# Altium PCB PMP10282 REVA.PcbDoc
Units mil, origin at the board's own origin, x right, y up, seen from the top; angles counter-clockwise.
Board outline 3149.61 x 1181.1 mil, 4 copper layers (Top Layer, MidLayer1, MidLayer2, Bottom Layer), stack 62.2 mil thick; 58 components, 35 nets, 158 pads, 79 vias.
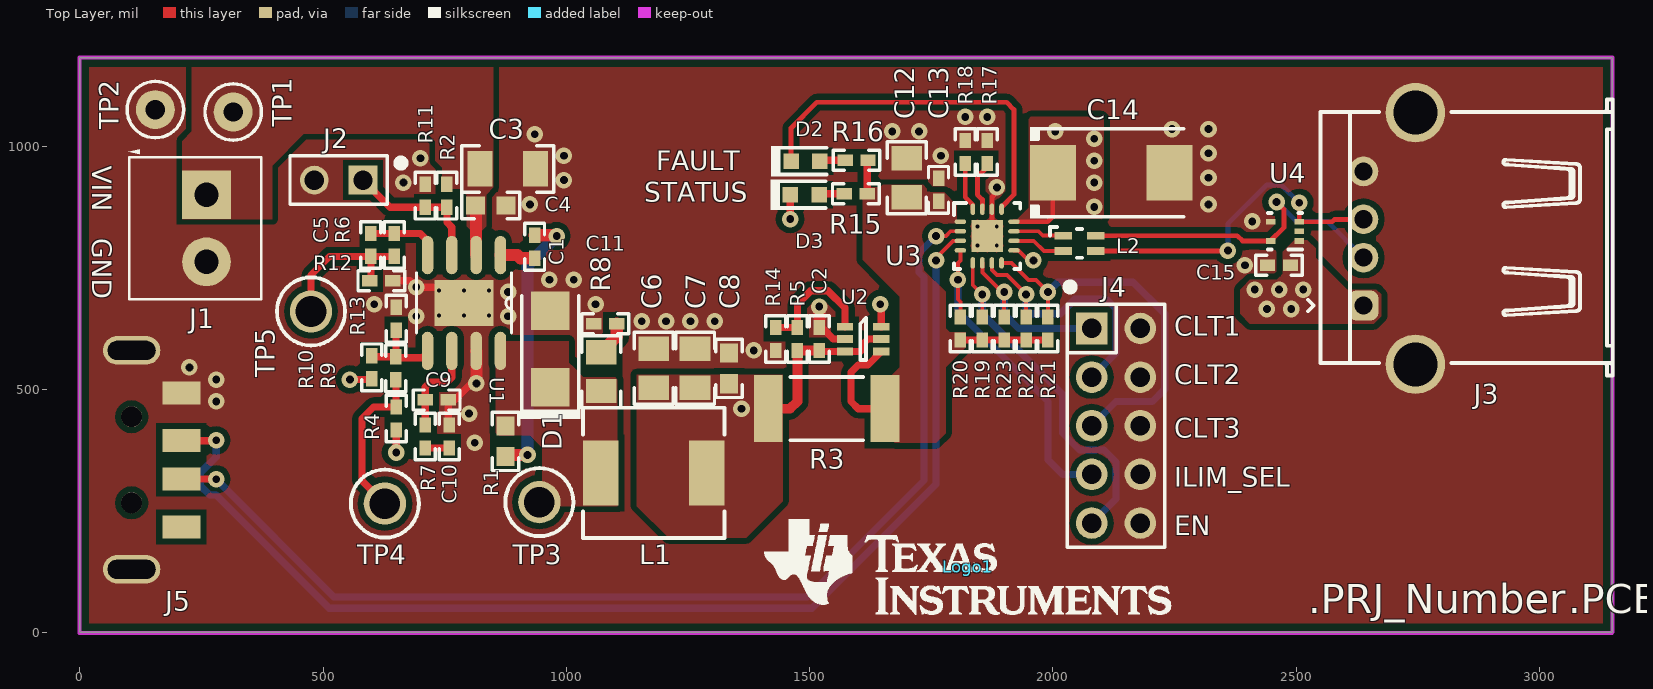
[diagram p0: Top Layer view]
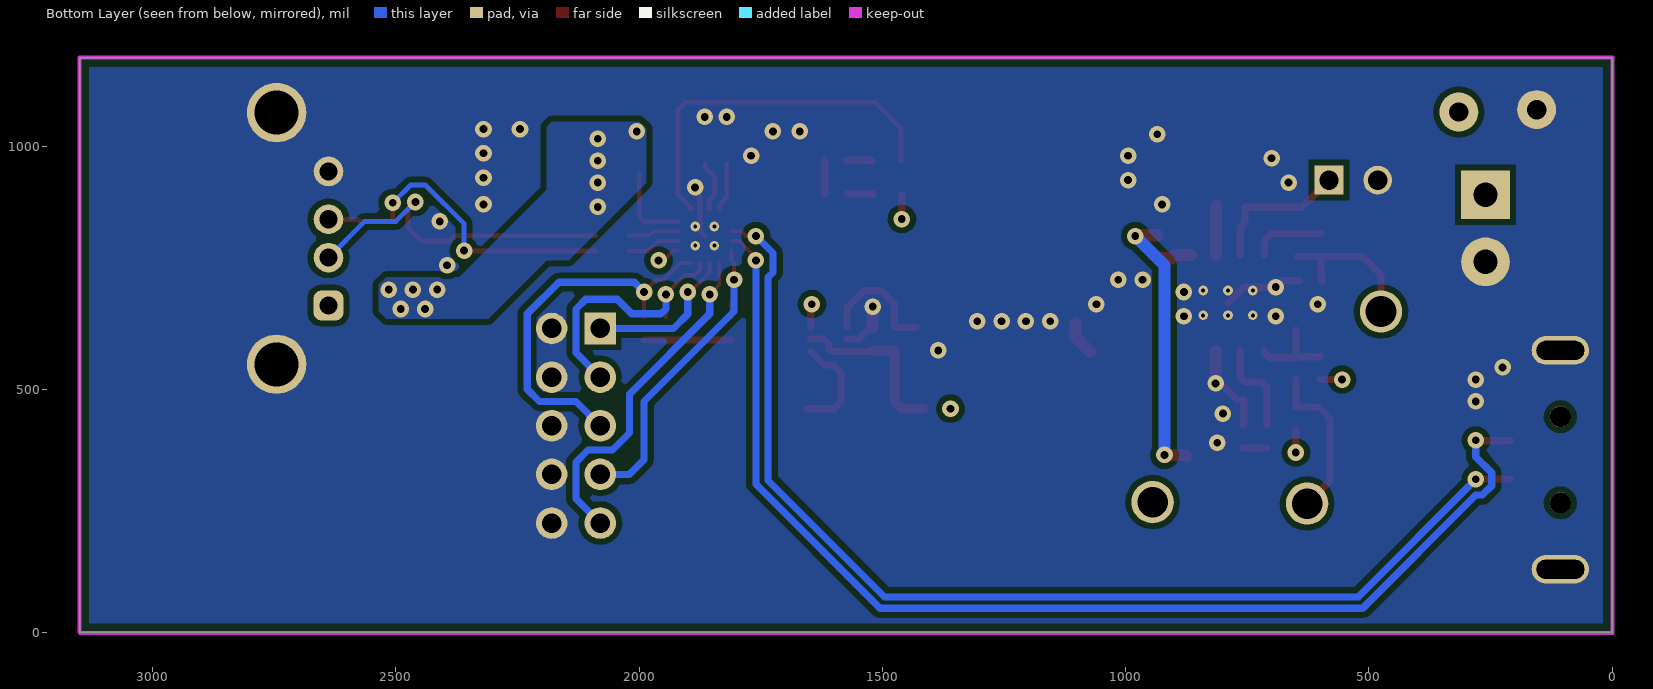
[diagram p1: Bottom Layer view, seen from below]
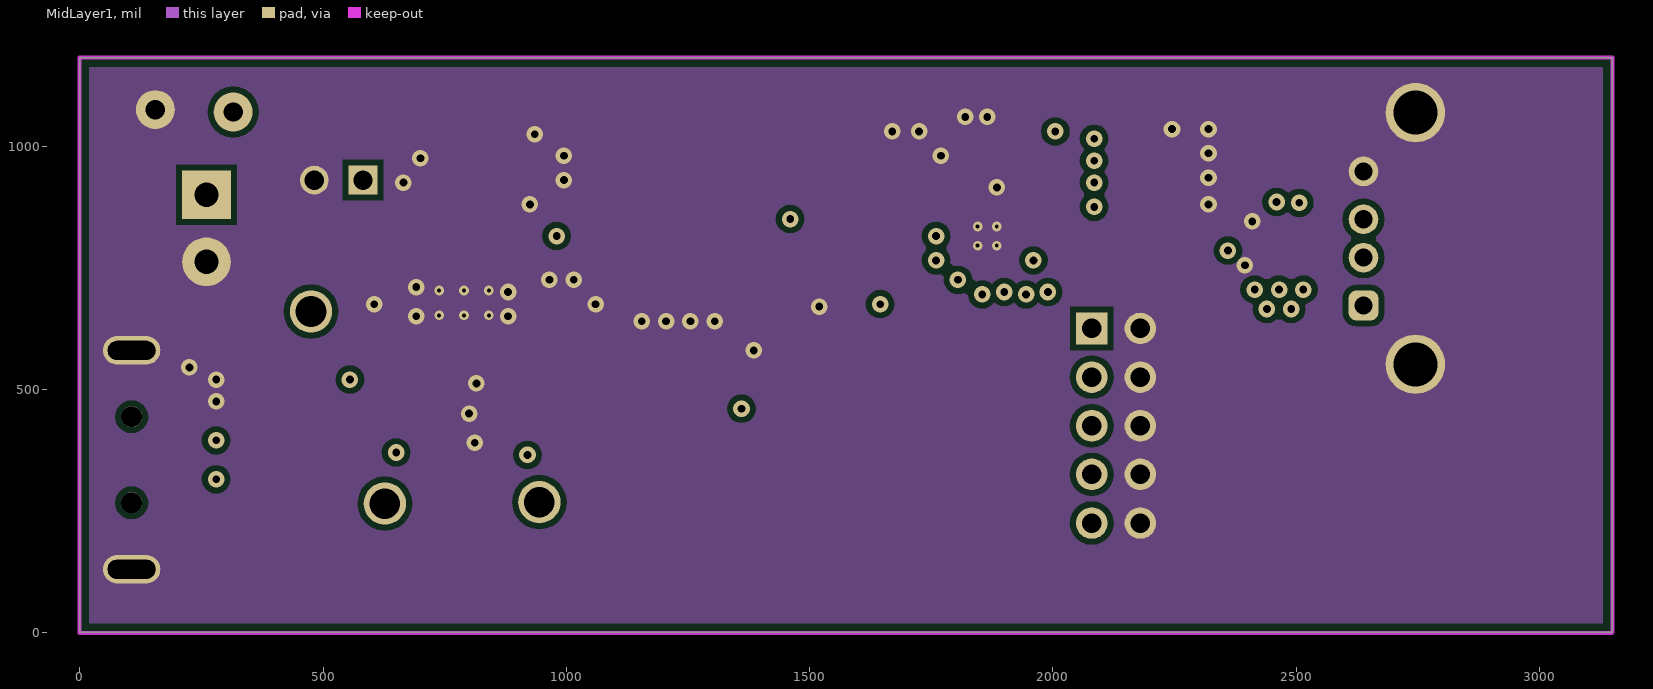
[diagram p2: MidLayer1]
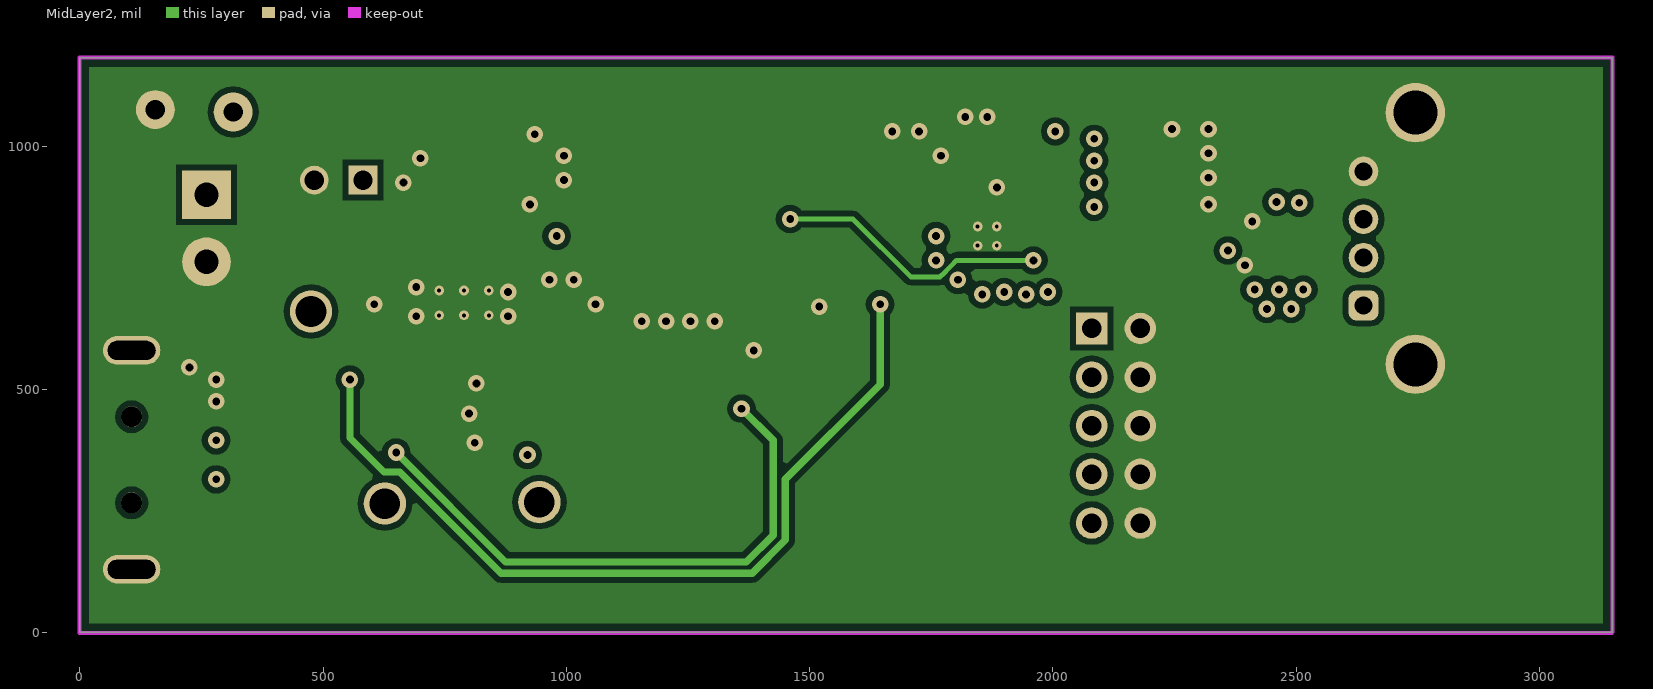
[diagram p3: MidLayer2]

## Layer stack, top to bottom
Top Layer: signal copper 1.4
Dielectric: core 22, FR-4, Dk 4.8
MidLayer1: signal copper 1.4
Dielectric: prepreg 12.6, FR-4, Dk 4.8
MidLayer2: signal copper 1.4
Dielectric: core 22, FR-4, Dk 4.8
Bottom Layer: signal copper 1.4

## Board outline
0,0 3149.61,0 3149.61,1181.1 0,1181.1

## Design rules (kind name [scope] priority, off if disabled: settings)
AcuteAngle [All] p1: minimum=4.50000000000000E+0001 checktracksonly=FALSE
AssemblyTestPointUsage [All] p1: valid=2
Clearance Clearance_BoardEdge_MountingHoles [OnCopper and InComponentClass('Mounting Holes') vs IsKeepOut] p1: gap=25
Clearance Clearance_BoardEdge_Poly [OnCopper and InPoly vs IsKeepOut] p2: gap=15
Clearance Clearance_BoardEdge [OnCopper and Not InComponentClass('Logo') and not InComponentClass('FiducialMark') and not InRegion(1000,500,4000,800) and Not IsKeepout vs IsKeepOut] p3: gap=25
Clearance Clearance_Poly [InPolygon] p4: gap=12
Clearance [All] p5: gap=8
ComponentClearance ComponentClearance_Shunt [InComponentClass('Header') vs InComponentClass('Shunt')] p1: gap=0 collisioncheckmode=3 verticalgap=0 showdistances=FALSE
ComponentClearance ComponentClearance_Logo [InComponentClass('Logo')] p2: gap=0 collisioncheckmode=3 verticalgap=0 showdistances=FALSE
ComponentClearance ComponentClearance_ScrewToNut [(HasFootprint('NY PMS 440 0025 PH')) vs (HasFootprint('Keystone_1902C'))] p3: gap=5 collisioncheckmode=3 verticalgap=10 showdistances=FALSE
ComponentClearance ComponentClearance_MountingHoles [InComponentClass('Mounting Holes')] p4: gap=250 collisioncheckmode=3 verticalgap=100000 showdistances=FALSE
ComponentClearance ComponentClearance_SmallPassives [HasFootprint('0201*') or HasFootprint('0402*') or HasFootprint('0508') or HasFootprint('0603*') or HasFootprint('0612') or HasFootprint('0805*') or HasFootprint('0815*') or HasFootprint('0830*') or HasFootprint('1206*') or HasFootprint('1210*') or HasFootprint('1808*') or HasFootprint('1812*') or HasFootprint('1825*') or HasFootprint('2010*') or HasFootprint('2220*') or HasFootprint('2225*') or HasFootprint('2512*') or HasFootprint('2728*') or HasFootprint('3518*') vs HasFootprint('0201*') or HasFootprint('0402*') or HasFootprint('0508') or HasFootprint('0603*') or HasFootprint('0612') or HasFootprint('0805*') or HasFootprint('0815*') or HasFootprint('0830*') or HasFootprint('1206*') or HasFootprint('1210*') or HasFootprint('1808*') or HasFootprint('1812*') or HasFootprint('1825*') or HasFootprint('2010*') or HasFootprint('2220*') or HasFootprint('2225*') or HasFootprint('2512*') or HasFootprint('2728*') or HasFootprint('3518*')] p5: gap=20 collisioncheckmode=3 verticalgap=10 showdistances=FALSE
ComponentClearance ComponentClearance_THtoSMT [IsThruComponent vs IsSMTComponent] p6: gap=25 collisioncheckmode=3 verticalgap=30 showdistances=FALSE
ComponentClearance ComponentClearance_THtoTH [IsThruComponent vs IsThruComponent] p7: gap=50 collisioncheckmode=3 verticalgap=30 showdistances=FALSE
ComponentClearance [All] p8: gap=20 collisioncheckmode=3 verticalgap=10 showdistances=FALSE
DiffPairsRouting [All] p1: maxlimit=100 minlimit=10 mostfreqgap=10 maxuncoupledlength=1000
FabricationTestPointUsage TestPointUsage [All] p1: valid=2 allowmultiple=FALSE
FabricationTestpoint Testpoint [All] p1: side=3 testpointundercomponent=TRUE minsize=40 maxsize=100 preferedsize=60 minholesize=0 maxholesize=40 preferedholesize=32 testpointgrid=1 allowsidetop=TRUE allowsidebottom=TRUE usegrid=TRUE gridtolerance=0.01
FanoutControl Fanout_LCC [IsLCC] p1: bgadir=Out bgaviamode=Centered fanoutstyle=Auto fanoutdirection=Alternating viagrid=1 // Fanout_LCC (Default Rule)
FanoutControl Fanout_BGA [IsBGA] p2: bgadir=Out bgaviamode=Centered fanoutstyle=Auto fanoutdirection=Alternating viagrid=1 // Fanout_BGA (Default Rule)
FanoutControl Fanout_Default [All] p4: bgadir=Out bgaviamode=Centered fanoutstyle=Auto fanoutdirection=Alternating viagrid=1 // Fanout_Default (Default Rule)
FanoutControl Fanout_Small [(CompPinCount < 5)] p5: bgadir=Out bgaviamode=Centered fanoutstyle=Auto fanoutdirection=OutThenIn viagrid=1 // Fanout_Small (Default Rule)
HoleSize [All] p1: absolutevalues=TRUE maxlimit=251 minlimit=8 maxpercent=80.000 minpercent=20.000
MinimumAnnularRing MinimumAnnularRing_ThermalPadVias [IsVia and InAnyComponent] p1: minimumring=5.91
MinimumAnnularRing [All] p2: minimumring=9
MinimumSolderMaskSliver MinimumSolderMaskSliver_Logo [InComponentClass('Logo') vs InComponentClass('Logo')] p1: minsoldermaskwidth=0.7
MinimumSolderMaskSliver [All] p2: minsoldermaskwidth=3
PlaneClearance [All] p1: clearance=15
PlaneConnect [All] p1: planeconnectstyle=Direct reliefexpansion=10 reliefentries=4 reliefconductorwidth=10 reliefairgap=10
PolygonConnect [All] p1: connectstyle=Direct reliefconductorwidth=10 reliefentries=4 polygonreliefangle="90 Angle" airgapwidth=10
RoutingVias ThermalPadVias [IsVia and InAnyComponent] p1: holewidth=7.87 width=19.68 viastyle="Through Hole" minholewidth=7.87 minwidth=19.68 maxholewidth=12.99 maxwidth=23.62
RoutingVias [All] p2: holewidth=16 width=34 viastyle="Through Hole" minholewidth=7.87 minwidth=26 maxholewidth=40 maxwidth=65
SMDToCorner [All] p1: distance=30000
SilkToSilkClearance [All] p1: silktosilkclearance=0
SilkscreenOverComponentPads [All] p1: minsilkscreentomaskgap=0
SolderMaskExpansion [All] p1: expansion=1.97
Width [All] p1: maxlimit=100 minlimit=6 preferedwidth=10 checkconnectedcopper=TRUE
13 further rules are at their usual default settings.

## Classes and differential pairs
component class Logo: Logo1
component class Header: J2

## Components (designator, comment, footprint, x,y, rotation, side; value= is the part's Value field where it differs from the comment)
C1 "C1005X7R1H104K050BB" 0402 934.5,792.99 r270 top
C2 "C1005X7R1H104K050BB" 0402 1520,603.19 r90 top
C3 "GRM31CR71H475KA12L" 1206 879.5,952.99 r0 top
C4 "UMK107AB7105KA-T" 0603 844.5,877.99 r0 top
C5 "" 0402 598.12,796.77 r270 top
C6 "GRM21BR61A226ME44" 0805_HV 1179.5,542.99 r90 top
C7 "GRM21BR61A226ME44" 0805_HV 1264.5,542.99 r90 top
C8 "UMK107AB7105KA-T" 0603 1334.5,542.99 r90 top
C9 "GRM1535C1H101JDD5D" 0402 733.28,477.99 r0 top
C10 "C1005C0G1E102J" 0402 759.5,402.99 r90 top
C11 "" 0402 1080,635 r180 top
C12 "GRM21BR71A106KE51L" 0805_HV 1700,935 r90 top
C13 "C1005X7R1H104K050BB" 0402 1765,910 r90 top
C14 "10TPB150ML" TPB_D4 2120,945 r0 top
C15 "C1005X7R1H104K050BB" 0402 2465,755 r180 top
D1 "B340LA-13-F" SMA 966.52,582.63 r90 top
D2 "LTST-C190GKT" LED_LTST-C190 1491.59,969 r180 top
D3 "LTST-C190GKT" LED_LTST-C190 1490,900 r180 top
J1 "ED555/2DS" TERM_BLK_ED555-2DS 260,900 r270 top
J2 "PEC02SAAN" CONN_PEC02SAAN 531.86,930 r180 top
J3 "676430910" MOLEX_0676430910 2745,810 r90 top
J4 "PEC05DAAN" CONN_PEC05DAAN 2130,425 r270 top
J5 "48037-1000" CONN_USB-A-48037-1000 120,355 r180 top
L1 "SPM6530T-3R3M" SPM6530 1179.5,327.99 r0 top
L2 "985DH-1026" NT2012 2055,800 r0 top
Logo1 "Texas Instruments" TI_Stacked_Overlay_Small 1825,135 r0 top
R1 "CRCW06035R11FKEA" 0603 874.5,392.99 r270 top
R2 "CRCW0402365KFKED" 0402 754.5,897.99 r90 top
R3 "ERJ-M1WSF10MU" 2512M 1535,460 r0 top
R4 "CRCW040251R1FKED" 0402 650,440 r270 top
R5 "CRCW040210K0FKED" 0402 1475,603.19 r270 top
R6 "CRCW040247K5FKED" 0402 646.31,796.77 r90 top
R7 "CRCW040224K3FKED" 0402 709.5,402.99 r90 top
R8 "" 0805_HV 1071.52,536.29 r270 top
R9 "CRCW04028K25FKED" 0402 649.5,542.99 r270 top
R10 "CRCW040213K0FKED" 0402 600,545 r90 top
R11 "CRCW040286K6FKED" 0402 709.5,897.99 r270 top
R12 "CRCW04020000Z0ED" 0402 619.5,722.99 r180 top
R13 "CRCW04021K21FKED" 0402 650,645 r270 top
R14 "CRCW040210K0FKED" 0402 1430,603.19 r90 top
R15 "CRCW04022K20JNED" 0402 1595,901.81 r0 top
R16 "CRCW04022K20JNED" 0402 1596.59,970.81 r0 top
R17 "CRCW040248K7FKED" 0402 1865,987.72 r270 top
R18 "CRCW040222K1FKED" 0402 1820,987.72 r270 top
R19 "CRCW0402100KFKED" 0402 1855,625 r270 top
R20 "CRCW0402100KFKED" 0402 1810,625 r270 top
R21 "CRCW0402100KFKED" 0402 1990,625 r270 top
R22 "CRCW0402100KFKED" 0402 1945,625 r270 top
R23 "CRCW0402100KFKED" 0402 1900,625 r270 top
TP1 "5000" Keystone5000 315,1070 r0 top
TP2 "5001" Keystone5001 155,1075 r0 top
TP3 "5010" Keystone5010 944.5,267.99 r270 top
TP4 "5010" Keystone5010 626.86,265 r270 top
TP5 "5010" Keystone5010 475,660 r270 top
U1 "TPS54340QDDAQ1" DDA0008E_N 789.5,677.4 r270 top
U2 "INA213AQDCKRQ1" DCK0006A_N 1610,603.19 r0 top
U3 "TPS2546QRTERQ1" RTE0016C 1865,815 r0 top
U4 "TPD2E001IDRLRQ1" DRL0005A 2477.09,824.66 r180 top

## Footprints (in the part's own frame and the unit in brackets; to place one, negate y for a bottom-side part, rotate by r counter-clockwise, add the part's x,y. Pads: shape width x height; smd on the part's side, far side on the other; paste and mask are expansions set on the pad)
0402 [mm] "0402 from SM-752 data"
  rect 0.8x0.6 smd: 1(-0.6,0) 2(0.6,0)
  silkscreen extent -1.22,-0.52 1.22,0.52, body extent -0.55,-0.3 0.55,0.3, height 0.6
0603 [mm] "0603 from SM-752 data"
  rect 1x0.95 smd: 1(-0.8,0) 2(0.8,0)
  silkscreen extent -1.52,-0.69 1.52,0.69, body extent -0.87,-0.47 0.87,0.47, height 0.85
0805_HV [mil] "0805 with 30mil clearance between pads"
  rect 50x63 smd: 1(-40,0) 2(40,0)
  silkscreen extent -74,-40 74,40, body extent -43,-29 43,29, height 43
1206 [mm] "1206 from SM-752 data"
  rect 1.3x1.85 smd: 1(-1.45,0) 2(1.45,0)
  silkscreen extent -2.4,-1.21 2.4,1.21, body extent -1.7,-0.9 1.7,0.9, height 1.35
2512M [mm] "Chip Resistor, Body 6.3x3.2mm, IPC Low Density"
  rect 1.5x3.5 smd: 1(-3.05,0) 2(3.05,0)
  silkscreen extent -1.9,-1.65 1.9,1.65, body extent -3.22,-1.67 3.22,1.67, height 0.71
CONN_PEC02SAAN [mm] "SULLINS"
  rect 1.5x1.5 hole 1.016: 1(-1.27,0)
  round 1.5 hole 1.016: 2(1.27,0)
  silkscreen extent -3.45,-1.27 2.54,1.27, body extent -2.54,-1.27 2.54,1.27, height 8.38
CONN_PEC05DAAN [mm] "SULLINS"
  rect 1.65x1.65 hole 1.016 mask+0: 1(-5.08,-1.27)
  round 1.65 hole 1.016 mask+0: 2(-5.08,1.27) 3(-2.54,-1.27) 4(-2.54,1.27) 5(0,-1.27) 6(0,1.27) 7(2.54,-1.27) 8(2.54,1.27) 9(5.08,-1.27) 10(5.08,1.27)
  silkscreen extent -7.45,-2.6 6.35,2.54, body extent -6.35,-2.54 6.35,2.54, height 8.38
CONN_USB-A-48037-1000 [mm] "Molex"
  rect 2x1.2 smd: 1(-2.25,3.5) 2(-2.25,1) 3(-2.25,-1) 4(-2.25,-3.5)
  round 1.092 hole 1.092 unplated: 5(0.35,2.248) 6(0.35,-2.248)
  oval 3x1.5 hole 1 slot 2.5 at 0 deg: 7(0.35,-5.715) 8(0.35,5.715)
  body extent -3.13,-6.35 18.15,6.35, height 3.09
DCK0006A_N [mm] "SOT23, 6-Leads, Body 2x1.3mm, Pitch 0.65mm, Lead Span 2.1mm, IPC Medium Density"
  rect 0.85x0.4 smd: 1(-0.95,0.65) 2(-0.95,0) 3(-0.95,-0.65) 4(0.95,-0.65) 5(0.95,0) 6(0.95,0.65)
  silkscreen extent -0.15,-1.1 0.15,1.1, body extent -1.14,-1 1.14,1, height 0.94
DDA0008E_N [mm]
  oval 2x0.6 smd: 1(-2.5,1.905) 2(-2.5,0.635) 3(-2.5,-0.635) 4(-2.5,-1.905) 5(2.5,-1.905) 6(2.5,-0.635) 7(2.5,0.635) 8(2.5,1.905)
  rect 2.4x3.1 smd: 9(0,0)
  silkscreen extent -1.58,-2.49 1.58,2.49, body extent -2.98,-2.45 2.98,2.45, height 1.5
DRL0005A [mm] "SOTFL, 5-Flat Leads, Body 1.2x1.6x0.6mm, Pitch 0.5mm, TI recommended"
  rect 0.5x0.3 smd: 1(-0.75,0.5) 2(-0.75,0) 3(-0.75,-0.5) 4(0.75,-0.5) 5(0.75,0.5)
  silkscreen extent -0.9,-0.95 0.9,0.95, body extent -0.85,-0.85 0.85,0.85, height 0.62
Keystone5000 [mil] "For Keystone 500x miniature loop terminals"
  round 80 hole 40: 1(0,0)
  silkscreen extent -58,-58 58,58, body extent -49,-49 49,49, height 182
Keystone5001 [mil] "For Keystone 500x miniature loop terminals"
  round 80 hole 40: 1(0,0)
  silkscreen extent -58,-58 58,58, body extent -49,-49 49,49, height 182
Keystone5010 [mil] "Keystone Multipurpose loops"
  round 87 hole 63: 1(0,0)
  silkscreen extent -70,-70 70,70, body extent -63,-63 63,62, height 319
LED_LTST-C190 [mm] "Lite-On"
  rect 0.8x0.8 smd: 1(-0.75,0) 2(0.75,0)
  silkscreen extent -1.1,-0.8 1.8,0.8, body extent -0.85,-0.45 0.85,0.45, height 0.9
MOLEX_0676430910 [mm] "MOLEX"
  rrect50% 1.55x1.55 hole 0.95: 1(-3.5,2.7)
  round 1.55 hole 0.95: 2(-1,2.7) 3(1,2.7) 4(3.5,2.7)
  round 3.1 hole 2.3: 5(-6.57,-0.01) 6(6.57,-0.01)
  silkscreen extent -7.15,-10.31 7.25,5.6, body extent -8,-10.25 8,5.01, height 7.73
NT2012 [mm] "TOKO"
  rect 0.9x0.4 smd: 1(-0.85,0.4) 3(-0.85,-0.4) 4(0.85,-0.4) 6(0.85,0.4)
  silkscreen extent -1.55,-0.75 0.13,0.85, body extent -1.1,-0.7 1.1,0.7, height 1.31
RTE0016C [mm] "Texas Insturments"
  oval 0.6x0.24 smd paste+0: 1(-1.4,0.75) 2(-1.4,0.25) 3(-1.4,-0.25) 4(-1.4,-0.75) 9(1.4,-0.75) 10(1.4,-0.25) 11(1.4,0.25) 12(1.4,0.75)
  oval 0.24x0.6 smd paste+0: 5(-0.75,-1.4) 6(-0.25,-1.4) 7(0.25,-1.4) 8(0.75,-1.4) 13(0.75,1.4) 14(0.25,1.4) 15(-0.25,1.4) 16(-0.75,1.4)
  rect 1.66x1.66 smd paste-0.88: 17(0,0)
  silkscreen extent -1.73,-1.73 1.73,1.73, body extent -1.58,-1.58 1.58,1.58, height 0.81
SMA [mm] "Molded Diode, 2-Leads, Body 4.3x2.6mm, IPC Medium Density, based on OnSemi component dimensions and land pattern"
  rect 2x2 smd: 1(-2,0) 2(2,0)
  silkscreen extent -3.66,-1.57 2.79,1.57, body extent -2.6,-1.3 2.6,1.3, height 2.42
SPM6530 [mm] "TDK"
  rect 1.85x3.4 smd: 1(-2.775,0) 2(2.775,0)
  silkscreen extent -3.7,-3.4 3.7,3.4, body extent -3.7,-3.4 3.7,3.4, height 3.3
TERM_BLK_ED555-2DS [mil]
  rect 100x100 hole 50: 1(0,0)
  round 100 hole 50: 2(138,0)
  silkscreen extent -93,-161 215,113, body extent -69,-150 207,106, height 323
TI_Stacked_Overlay_Small [mil]
  silkscreen extent -418,-98 418,98
TPB_D4 [mm] "Panasonic recommended land pattern for size code D4"
  rect 2.4x2.9 smd: 1(-3.05,0) 2(3.05,0)
  silkscreen extent -4.25,-2.39 3.8,2.39, body extent -3.8,-2.3 3.8,2.3, height 4.01

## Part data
C1 C2 C13 C15: "CAP, CERM, 0.1uF, 50V, +/-10%, X7R, 0402"
C3: "CAP, CERM, 4.7uF, 50V, +/-10%, X7R, 1206"
C4 C8: "CAP, CERM, 1uF, 50V, +/-10%, X7R, 0603"
C5: library part C1005X7R1H104K050BB, "CAP, open, 0402"
C6 C7: "CAP, CERM, 22uF, 10V, +/-20%, X5R, 0805"
C9: "CAP, CERM, 100pF, 50V, +/-5%, C0G/NP0, 0402"
C10: "CAP, CERM, 1000pF, 25V, +/-5%, C0G/NP0, 0402"
C11: library part C1005C0G1E102J, "CAP, open, 0402"
C12: "CAP, CERM, 10uF, 10V, +/-10%, X7R, 0805"
C14: library part 10TPB220M, "CAP, 150uF, 10V, +/-20%, 0.04 ohm, SMD"
D1: "Diode, Schottky, 40V, 3A, SMA"
D2 D3: "LED, Green, SMD"
J1: "Terminal Block, 6A, 3.5mm Pitch, 2-Pos, TH"
J2: "Header, 100mil, 2x1, Tin, TH"
J3: "Connector, Receptacle, USB Standard, R/A, Top Mount TH"
J4: "Header, 100mil, 5x2, Tin plated, TH"
J5: "Connector, Plug, USB Type A, R/A, Top Mount SMT"
L1: "Inductor, Shielded, Ferrite, 3.3uH, 6.8A, 0.0297 ohm, SMD"
L2: library part 985DH-1023, "Coupled inductor, 0.28A, 0.36 ohm, SMD"
Logo1: library part TI_Logo, "Texas Instrument Corporate Signature"
R1: "RES, 5.11 ohm, 1%, 0.1W, 0603"
R2: "RES, 365k ohm, 1%, 0.063W, 0402"
R3: "RES, 0.01 ohm, 1%, 1W, 2512"
R4: "RES, 51.1 ohm, 1%, 0.063W, 0402"
R5 R14: "RES, 10.0k ohm, 1%, 0.063W, 0402"
R6: "RES, 47.5k ohm, 1%, 0.063W, 0402"
R7: "RES, 24.3k ohm, 1%, 0.063W, 0402"
R8: library part CRCW08051K78FKEA, "RES, open, 0805"
R9: "RES, 8.25k ohm, 1%, 0.063W, 0402"
R10: "RES, 13.0k ohm, 1%, 0.063W, 0402"
R11: "RES, 86.6k ohm, 1%, 0.063W, 0402"
R12: "RES, 0 ohm, 5%, 0.063W, 0402"
R13: "RES, 1.21k ohm, 1%, 0.063W, 0402"
R15 R16: "RES, 2.2k ohm, 5%, 0.063W, 0402"
R17: "RES, 48.7k ohm, 1%, 0.063W, 0402"
R18: "RES, 22.1k ohm, 1%, 0.063W, 0402"
R19 R20 R21 R22 R23: "RES, 100k ohm, 1%, 0.063W, 0402"
TP1: "Test Point, TH, Miniature, Red"
TP2: "Test Point, TH, Miniature, Black"
TP3 TP4 TP5: "Test Point, Multipurpose, Red, TH"
U1: library part TPS54340DDA, "42 V Input, 3.5 A, Step Down DC-DC Converter with Eco-mode, DDA0008E"
U2: library part INA213AIDCK, "Voltage Output, High or Low Side Measurement, Bi-Directional Zero-Drift Series Current-Shunt Monitor, DCK0006A"
U3: library part TPS2546RTE, "USB Charging Port Controller and Power Switch with Load Detection, RTE0016C"
U4: "Automotive Catalog Low-Capacitance + / - 15 kV ESD-Protection Array for High-Speed Data Inter, 2 Channels, -40 to +85 degC, 5-pin SOT (DRL), Green (RoHS & no Sb/Br)"

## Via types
v1: diameter 34, hole 16, Top Layer to Bottom Layer, 69 vias
v2: diameter 19.68, hole 7.87, Top Layer to Bottom Layer, tented top, 6 vias
v3: diameter 19.68, hole 7.87, Top Layer to Bottom Layer, 4 vias

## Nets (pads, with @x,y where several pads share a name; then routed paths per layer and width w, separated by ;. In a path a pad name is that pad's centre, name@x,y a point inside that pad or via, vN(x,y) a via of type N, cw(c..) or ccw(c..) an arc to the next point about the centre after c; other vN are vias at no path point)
GND: C2.2 C3.2 C4.2 C6.2 C7.2 C8.2 C9.2 C10.2 C11.2 C12.2 C13.2 C14.2 C15.2 D1.2 J1.2 J2.2 J3.4 J3.5 J3.6 J4.2 J4.4 J4.6 J4.8 J4.10 J5.4 J5.7 J5.8 R11.1 R12.1 R13.1 R14.1 R17.1 R18.1 TP2.1 U1.7 U1.9 U2.2 U3.14 U3.17 U4.4 | length 570.9
  Top Layer w10: U3.17 1874.84,824.84 U3.14 1874.84,889.84 1875,890 1875,895 1885,905 v1(1885,915)
  Top Layer w15: R12.1 678.52,722.99 v1(691.5,710) 756.9,710 U1.9 ; C10.2 756.9,429.21 C9.2 770.48,477.99 804.54,512.04 v1(815,512.04) ; C2.2 1524.84,626.81 1548.46,603.19 U2.2
  Top Layer w25: U1.7 815,578.47 v1(815,512.04) ; C2.2 v1(1520,670)
  other v1: 811.5,390 800,450 280,475 280,520 225,545 1385,580 1155,640 1205,640 1255,640 1305,640 691.5,650 880,650 605,675 1060,675 880,700 965,725 1015,725 2395,755 2410,845 925,880 2320,880 665,925 995,930 2320,935 700,975 995,980 1770,980 2320,985 935,1024.25 1670,1030 1725,1030 2245,1035 2320,1035 1820,1060 1865,1060
  other v2: 738.32,651.81 789.5,651.81 840.68,651.81 738.32,702.99 789.5,702.99 840.68,702.99
  other v3: 1845.31,795.32 1884.68,795.32 1845.31,834.68 1884.68,834.68
NetC1_1: C1.1 R1.2 | length 568
  Top Layer w25: R1.2 878.01,365 v1(920,365) ; C1.1 978.39,816.61 v1(980,815)
  Bottom Layer w25: v1(920,365) 920,755 v1(980,815)
NetC1_2: C1.2 U1.1 | length 72.7
  Top Layer w25: U1.1 899.18,775.82 905.63,769.36 C1.2
NetC2_1: C2.1 C6.1 C7.1 C8.1 L1.2 R3.1 R4.2 R5.2 U2.3 U2.5 | length 1584.6
  Top Layer w15: v1(650,370) R4.2 ; C2.1 1521.97,577.6 U2.3 1604.09,577.6 1610,583.5 1610,593.19 1620,603.19 U2.5
  Top Layer w20: R3.1 1460,460 1475,475 R5.2 C2.1
  MidLayer2 w15: v1(650,370) 875,145 1370,145 1425,200 1425,395 v1(1360,460)
NetC3_1: C3.1 C4.1 J1.1 R2.2 TP1.1 U1.2 | length 102.8
  Top Layer w25: C4.1 814.5,876.49 U1.2
NetC5_1: C5.1 R6.2 U1.4 | length 152.2
  Top Layer w15: C5.1 R6.2 699.61,820.39 714.5,805.5 U1.4
NetC5_2: C5.2 R6.1 R12.2 TP5.1 | length 313.2
  Top Layer w15: TP5.1 475,735 513.14,773.14 C5.2 ; R12.2 598.12,725.23 C5.2 ; R6.1 C5.2
NetC9_1: C9.1 R7.2 U1.6 | length 195.6
  Top Layer w15: R7.2 709.66,426.77 C9.1 709.66,504.66 720,515 755,515 764.5,524.5 U1.6
NetC10_1: C10.1 R7.1 | length 50
  Top Layer w15: R7.1 C10.1
NetC11_1: C11.1 R8.1 | length 72
  Top Layer w25: R8.1 1103.62,608.4 C11.1
NetC12_1: C12.1 C13.1 R3.2 R15.2 R16.2 R19.2 R20.2 R21.2 R22.2 R23.2 U2.4 U3.1 | length 466
  Top Layer w15: R15.2 1618.62,969.22 R16.2 ; U2.4 1619.84,550.04 1600.04,550.04 1585,535 1585,475 1600,460 R3.2 ; R20.2 R19.2 R23.2 R22.2 R21.2
NetC14_1: C14.1 C15.1 J3.1 U3.12 U4.1 | length 174.2
  Top Layer w10: U3.12 1989.53,844.53 1999.92,854.92 C14.1
  other v1: 2440,665 2490,665 2415,705 2465,705 2515,705 2085,875 2085,925 2085,970 2085,1015 2005,1030
NetD1_1: D1.1 L1.1 R1.1 R8.2 TP3.1 U1.8
NetD2_1: D2.1 R16.1 | length 52.6
  Top Layer w15: D2.1 1522.93,970.81 R16.1
NetD2_2: D2.2 U3.13 | length 769.6
  Top Layer w10: D2.2 1462.06,1037.06 1515,1090 1905,1090 1920,1075 1920,900 1894.53,874.53 U3.13
NetD3_1: D3.1 R15.1 | length 52.6
  Top Layer w15: D3.1 1521.34,901.81 R15.1
NetD3_2: D3.2 U3.9 | length 661.5
  Top Layer w8: U3.9 1929.53,785.47 1950,765 v1(1960,765)
  Top Layer w15: v1(1460,850) D3.2@1460,899.53
  MidLayer2 w10: v1(1460,850) 1589,850 1708,731 1768,731 1772,735 1772.43,735 1790,752.57 1790,753 1802,765 v1(1960,765)
NetJ2_1: J2.1 R2.1 R11.2 U1.3 | length 298.4
  Top Layer w15: J2.1 637.49,874.36 R11.2 R2.1 754.5,843.25 764.5,833.25 U1.3
NetJ3_2: J3.2 L2.6 U4.5 | length 687.2
  Top Layer w10: L2.6 2379.25,815.75 2390.03,804.97 U4.5 2475,832.41 2475,870 v1(2460,885)
  Bottom Layer w10: v1(2460,885) 2500,845 2564.33,845 J3.2
NetJ3_3: J3.3 L2.4 U4.3 | length 695
  Top Layer w10: L2.4 2359.25,784.25 v1(2360,785) ; v1(2506.62,883.38) U4.3 2574.34,844.34 2579.37,849.37 J3.3
  Bottom Layer w10: v1(2360,785) 2360,840 2440,920 2470,920 v1(2506.62,883.38)
NetJ4_1: J4.1 R23.1 U3.6 | length 370.3
  Top Layer w8: U3.6 1855.16,740.16 1895.32,700 v1(1900,700) R23.1
  Bottom Layer w15: v1(1900,700) 1900,654.51 1929.51,625 J4.1
NetJ4_3: J4.3 R22.1 U3.7 | length 553.2
  Top Layer w8: U3.7 1874.84,745.16 1885,735 1906.01,735 1945,696.01 v1(1945,695) R22.1
  Bottom Layer w15: v1(1945,695) 1945,665 1955,655 2015,655 2045,685 2110,685 2130,665 2130,575 J4.3
NetJ4_5: J4.5 R21.1 U3.8 | length 782.9
  Top Layer w8: U3.8 1914.88,759.88 1949.76,725 1965,725 v1(1990,700) R21.1
  Bottom Layer w15: v1(1990,700) 2010,720 2165,720 2230,655 2230,500 2205,475 2130,475 J4.5
NetJ4_7: J4.7 R20.1 U3.4 | length 690
  Top Layer w8: U3.4 1809.88,764.88 1805,760 v1(1805,725) 1805,685 1810,680 R20.1
  Bottom Layer w15: v1(1805,725) 1805,660 1990,475 1990,355 2020,325 J4.7
NetJ4_9: J4.9 R19.1 U3.5 | length 753.3
  Top Layer w8: U3.5 1835.47,714.53 v1(1855,695) R19.1
  Bottom Layer w15: v1(1855,695) 1855,655 2020,490 2020,410 2055,375 2105,375 2130,350 2130,275 J4.9
NetJ5_2: J5.2 U3.2 | length 2301.2
  Top Layer w8: v1(1760,815) 1780,815 1789.84,824.84 U3.2
  Top Layer w15: J5.2 279.37,315.63 v1(280,315)
  Bottom Layer w15: v1(280,315) 522,73 1495.47,73 1735,312.53 1735,730 1725,740 1725,780 v1(1760,815)
NetJ5_3: J5.3 U3.3 | length 2430.4
  Top Layer w8: v1(1760,765) 1760,770 1795.16,805.16 U3.3
  Top Layer w15: J5.3 279.37,394.37 v1(280,395)
  Bottom Layer w15: v1(280,395) 280,360.96 247.5,328.46 247.5,301.54 266.54,282.5 279.97,282.5 512.47,50 1505,50 1760,305 v1(1760,765)
NetL2_1: L2.1 U3.11 | length 105.2
  Top Layer w8: U3.11 1970.16,824.84 1979.25,815.75 L2.1
NetL2_3: L2.3 U3.10 | length 110.1
  Top Layer w8: U3.10 1960.85,805.16 1981.76,784.25 L2.3
NetR4_1: R4.1 R9.2 TP4.1 | length 330.1
  Top Layer w15: TP4.1 580,311.86 580,440 603.62,463.62 R4.1 649.5,464.12 R9.2
NetR5_1: R5.1 R14.2 U2.1 | length 255.3
  Top Layer w15: R14.2 R5.1 1475,675 1502.5,702.5 1537.5,702.5 1572.6,667.4 U2.1
NetR9_1: R9.1 R10.2 R13.2 U1.5 | length 179.8
  Top Layer w15: R10.2 602.01,566.61 R9.1 ; R13.2 649.5,620.88 R9.1 ; U1.5 715,578.47 715,575 705,565 651.11,565 R9.1
NetR10_1: R10.1 U2.6 | length 1816.9
  Top Layer w15: v1(555,520) 598.62,520 R10.1 ; v1(1645,675) 1647.4,672.6 U2.6
  MidLayer2 w15: v1(555,520) 555,400 625,330 657.47,330 865.47,122 1382,122 1450,190 1450,315 1645,510 v1(1645,675)
NetR17_2: R17.2 U3.15 | length 106.5
  Top Layer w10: U3.15 1855.16,889.84 1845,900 1845,936.85 1865,956.85 R17.2
NetR18_2: R18.2 U3.16 | length 100.4
  Top Layer w10: R18.2 1820,895 1835.47,879.53 U3.16
pads on no net: J5.1 J5.5 J5.6 U4.2

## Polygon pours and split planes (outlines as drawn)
GND on Top Layer "Top Layer-No Net 6" (solid, pour order 37): 0,1181.1 3149.61,1181.1 3149.61,2.5 3152.11,0 -2.5,0
NetC14_1 on Top Layer "Top Layer-No Net 5" (solid, pour order 27): 2520,810 2500,810 2475,785 2473,783 2473,766 2473,743 2473,738 2465,730 2460,725 2410,725 2405,725 2390,710 2385,705 2385,655 2405,635 2655.24,635 2660,635 2675,650 2675,695 2665,705 2605,705 2565,745 2540,770 2540,785 2540,790
NetC14_1 on Top Layer "Bottom Layer-No Net" (solid, pour order 25): 1950,872.99 1950,1055 1955,1060 1965,1060 2100,1060 2105,1055 2105,855 2100,850 2099.23,850.77 1995.77,850.77 1964.23,850.77 1960,855
NetC12_1 on Top Layer "Top Layer-No Net 4" (solid, pour order 20): 1655,525.94 1665.94,525.94 1685,545 1685,690 1608.76,766.24 1608.76,905.73 1618.03,915 1645,915 1650,920 1733.19,920 1748.19,905 1776.81,905 1802.99,878.82 1802.99,840 1745,840 1735,830 1735,745 1780,700 1780,625 1788,617 1820,617 1820,585 1780,545 1780,410 1760,390 1675,390 1655,410
NetC14_1 on Top Layer "Top Layer-No Net 3" (solid, pour order 18): 1927.01,840 1927.01,850 1950,872.99 1950,875 1950,885 1955,890 1965,900 1990,900 2035,900 2050,885 2050,860 2005,860 1985,840
NetC2_1 on Top Layer "Top Layer-No Net 2" (solid, pour order 6): 1145,530 1145,260 1210,195 1370,195 1445,270 1445,530
NetD1_1 on Top Layer "Top Layer-No Net 1" (solid, pour order 4): 1105,260 1105,520 1100,525 1035,525 1015,545 1005,555 1005,600 1003.9,598.9 855,598.9 855,410.8 855.8,410 860.8,405 865,405 925,405 950,380 950,260
NetC3_1 on Top Layer "Top Layer-No Net" (solid, pour order 2): 210,850 210,1000 210,1010 230,1030 230,1181.1 848.9,1181.1 850,1180 850,920 850,917.55 850,915 835,900 835,835 825,825 824,824 806,824 805,825 795,835 795,895 795,898.71 786.98,906.73 781.94,911.77 745,911.77 745,955 730,970 730,1010 715,1025 570,1025 460,1025 395,960 395,850
GND on Bottom Layer "Bottom Layer-No Net 2" (solid, pour order 31): -2.5,1181.1 3152.11,1181.1 3149.61,1178.6 3149.61,0 0,0
NetC14_1 on Bottom Layer "Bottom Layer-No Net 1" (solid, pour order 29): 1985,1035.55 1985,925 2050,860 2145,765 2185,765 2190,765 2280,675 2310,645 2520,645 2535,660 2535,715 2520,730 2400,730 2370,730 2190,910 2190,1040 2180,1050 2000,1050
GND on MidLayer2 "MidLayer2-No Net" (solid, pour order 33): -2.5,1181.1 3149.61,1181.1 3149.61,2.5 3152.11,0 3149.61,-2.5 0,-2.5
GND on MidLayer1 "MidLayer1-No Net" (solid, pour order 35): -2.5,1181.1 3149.61,1181.1 3149.61,-2.5 0,-2.5 -2.5,0

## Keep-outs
Keep-Out Layer:
  lines w5: 3149.61,-2.5 0,-2.5 ; 3152.11,0 3152.11,1181.1 ; -2.5,0 ccw(c0,0) 0,-2.5 ; -2.5,0 ccw(c0,0) 0,-2.5 ; -2.5,0 -2.5,1181.1 ; -2.5,1181.1 cw(c0,1181.1) 0,1183.6 ; -2.5,1181.1 cw(c0,1181.1) 0,1183.6 ; 0,1183.6 3149.61,1183.6 ; 3149.61,1183.6 cw(c3149.61,1181.1) 3152.11,1181.1 ; 3149.61,1183.6 cw(c3149.61,1181.1) 3152.11,1181.1
  lines w7.01: 0,0 3149.61,0 3149.61,1181.1 0,1181.1 0,0
  text ".Layer_Name" at 577,-858.49 h60

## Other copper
Top Layer:
  text ".Layer_Name" at 577,-858.49 h60
Bottom Layer:
  text ".Layer_Name" at 577,-858.49 h60

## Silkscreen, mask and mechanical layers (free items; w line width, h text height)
Top Overlay:
  text "VIN" at 25,960 h40 r270
  text "FAULT" at 1185,950 h40
  text "STATUS" at 1160,885 h40
  text "GND" at 25,810 h40 r270
  text "CLT1" at 2250,610 h40
  text "CLT2" at 2250,510 h40
  text "CLT3" at 2250,400 h40
  text "ILIM_SEL" at 2250,300 h40
  text "EN" at 2250,200 h40
  text ".PRJ_Number" at 2525,40 h60
  text ".PCB_Rev" at 3060,40 h60
  text ".Layer_Name" at 577,-858.49 h60
Bottom Overlay:
  text ".Layer_Name" at 577,-858.49 h60
Top Paste:
  text ".Layer_Name" at 577,-858.49 h60
Bottom Paste:
  text ".Layer_Name" at 577,-858.49 h60
Top Solder:
  text ".Layer_Name" at 577,-858.49 h60
  text ".Layer_Name" at 577,-858.49 h60
Bottom Solder:
  text ".Layer_Name" at 577,-858.49 h60
Drill Guide:
  text ".Layer_Name" at 577,-858.49 h60
M1 Board Outline:
  the board outline again, w7.01
  text ".Layer_Name" at 577,-858.49 h60
M2 Board Dimensions:
  rectangle: -0.5,-285.5 124.5,-160.5
  rectangle: 124.5,-410.5 499.5,-285.5
  lines w7: -0.5,-285.5 999.5,-285.5 ; 124.5,-410.5 124.5,-160.5 ; 249.5,-410.5 249.5,-160.5 ; 499.5,-410.5 499.5,-160.5 ; 749.5,-410.5 749.5,-160.5 ; -0.5,-410.5 999.5,-410.5 999.5,-160.5 -0.5,-160.5 -0.5,-410.5
  lines w10: -0.5,-475.5 -0.5,-455.5 ; 59.5,-485.5 -0.5,-465.5 ; 59.5,-445.5 -0.5,-465.5 ; 223.58,-465.5 -0.5,-465.5 ; 775.42,-465.5 999.5,-465.5 ; 939.5,-485.5 999.5,-465.5 ; 939.5,-445.5 999.5,-465.5 ; 999.5,-475.5 999.5,-455.5
  text "1000 (mil)" at 233.58,-501.49 h60
  text ".Layer_Name" at 577,-858.49 h60
M3 3D STEP Top:
  text ".Layer_Name" at 577,-858.49 h60
M4 3D STEP Bottom:
  text ".Layer_Name" at 577,-858.49 h60
M5 Assembly Top:
  lines w10: -292,-930.17 6308,-930.17 ; -292,-726.83 6310,-726.83 ; -292,-523.5 -292,-1133.5 3713,-1133.5 6310,-1133.5 6310,-523.5 -291.5,-523.5 -291.5,-1133.5 1284,-1133.5 ; 2173,-1133.5 2173,-523.5 ; 3440,-726.83 3440,-523.5 ; 4280,-726.83 4280,-523.5 ; 4902,-1140 4902,-937.17
  text "COMPONENTS MARKED 'DNP' SHOULD NOT BE POPULATED." at 1153.5,-318.5 h60
  text "ASSEMBLY VARIANT:" at 1153,-434 h60
  text ".VariantName" at 2189,-434 h60
  text "PCB VIEWED FROM TOP SIDE" at -228.5,-655.67 h60
  text "BOARD #:" at 2248,-655.67 h60
  text ".PRJ_Number" at 2793.5,-655.67 h60
  text "REV:" at 3638,-655.67 h60
  text ".PCB_Rev" at 3929.5,-655.67 h60
  text "SVN REV:" at 4476,-655.67 h60
  text ".VersionControl_RevNumber" at 4982,-655.67 h60
  text "IGNORE ->" at -228.5,-858.49 h60
  text "PLOT NAME =" at -228.5,-1064.34 h60
  text ".plot_File_Name" at 577,-1064.34 h60
  text "GENERATED    :" at 2250,-1064.34 h60
  text ".Print_Date" at 3119.5,-1064.34 h60
  text ".Print_Time" at 3848.5,-1064.34 h60
  text "TEXAS INSTRUMENTS" at 5113,-1064.34 h60
M6 Assembly Bottom:
  lines w10: -292.5,-727.33 6309.5,-727.33 ; -290.5,-930.67 6309.5,-930.67 ; 1115.5,-1140.5 1115.5,-937.67 ; 1737.5,-727.33 1737.5,-524 ; 2577.5,-727.33 2577.5,-524 ; 3844.5,-1134 3844.5,-524 ; 4733.5,-1134 6309,-1134 6309,-524 -292.5,-524 -292.5,-1134 2304.5,-1134 6309.5,-1134 6309.5,-524
  text "COMPONENTS MARKED 'DNP' SHOULD NOT BE POPULATED." at 6102,-318 h60
  text ".VariantName" at 5058,-434 h60
  text "ASSEMBLY VARIANT:" at 6097,-434 h60
  text ".VersionControl_RevNumber" at 1035.5,-656.17 h60
  text "SVN REV:" at 1541.5,-656.17 h60
  text ".PCB_Rev" at 2088,-656.17 h60
  text "REV:" at 2379.5,-656.17 h60
  text ".PRJ_Number" at 3224,-656.17 h60
  text "BOARD #:" at 3769.5,-656.17 h60
  text "PCB VIEWED FROM BOTTOM SIDE" at 6246,-656.17 h60
  text "IGNORE ->" at 2547.85,-858.49 h60
  text "TEXAS INSTRUMENTS" at 904.5,-1064.84 h60
  text ".Print_Time" at 2169,-1064.84 h60
  text ".Print_Date" at 2898,-1064.84 h60
  text "GENERATED    :" at 3767.5,-1064.84 h60
  text ".plot_File_Name" at 5440.5,-1064.84 h60
  text "PLOT NAME =" at 6246,-1064.84 h60
M9 Title Sheet:
  drawing of 57 lines, arcs and shapes, not listed
  text "1" at 739.84,8036.5 h70
  text "2" at 3235.5,8036.5 h70
  text "3" at 5724.84,8036.5 h70
  text "4" at 8231.51,8036.5 h70
  text "5" at 10730.5,8036.5 h70
  text "6" at 13235.5,8036.5 h70
  text "A" at -416.5,6893.5 h70
  text "A" at 14383.5,6893.5 h70
  text "B" at -416.5,4513.5 h70
  text "B" at 14383.5,4513.5 h70
  text "C" at -416.5,2138.5 h70
  text "C" at 14383.5,2138.5 h70
  text "PROJECT TITLE:" at 11343.5,277.5 h45
  text ".PRJ_Title" at 11393.5,144.17 h70
  text "DESIGNED FOR:" at 11343.5,-23.5 h45
  text ".PRJ_Customer" at 11393.5,-163.5 h70
  text "D" at -416.5,-231.5 h70
  text "D" at 14383.5,-231.5 h70
  text "FILE NAME:" at 11343.5,-323.5 h45
  text ".PCB_File_Name_No_Path" at 11393.5,-443.5 h70
  text "Texas Instruments (TI) and/or its licensors do not warrant the accuracy or completeness of this specification" at 6374,-605.34 h45
  text "ENGINEER:" at 11343.5,-613.5 h45
  text "LAYOUT BY:" at 12848.5,-613.5 h45
  text "or any information contained therein. TI and/or its licensors do not warrant that this design will meet" at 6329.01,-718 h45
  text ".PRJ_Engineer" at 11393.5,-768.49 h70
  text ".PCB_Layout" at 12899,-768.49 h70
  text "the specifications, will be suitable for your application or fit for any particular purpose, or will operate in" at 6329.01,-830.67 h45
  text ".Layer_Name" at 577,-858.49 h60
  text "ALTIUM DESIGNER VERSION:" at 12848.5,-923.5 h45
  text "an implementation. TI and/or its licensors do not warrant that the design is production worthy. You should" at 6329.01,-943.33 h45
  text "completely validate and test your design implementation to confirm the system functionality for your application." at 6374,-1056 h45
  text ".print_Scale" at 11393.5,-1056.83 h70
  text ".Application_BuildNumber" at 12899,-1056.83 h70
  text "1" at 739.84,-1263.5 h70
  text "2" at 3235.5,-1263.5 h70
  text "3" at 5724.84,-1263.5 h70
  text "4" at 8231.51,-1263.5 h70
  text "5" at 10730.5,-1263.5 h70
  text "6" at 13235.5,-1263.5 h70
M10 Fab Notes:
  drawing of 212 lines, arcs and shapes, not listed
  text "DESIGN INFORMATION" at 12381.02,6810 h60
  text "(REFER ALSO ARRAY/PANEL PROFILING INFORMATION)" at 12019.46,6648.29 h60
  text "BOARD SIZE" at 11333.46,6644 h60
  text "30MM" at 11795.78,6516.18 h60
  text "X" at 12301.46,6516.18 h60
  text "80MM" at 12532.78,6516.18 h60
  text "Number of Layers :" at 11736.46,6319 h60
  text "4" at 12831.27,6309 h60
  text "MIN. TRACK WIDTH:" at 11736.46,6180 h60
  text "8" at 12832.7,6180 h60
  text "MIL" at 12987.46,6180 h60
  text "MIN. CLEARANCE:" at 11736.46,6048 h60
  text "8" at 12832.7,6048 h60
  text "MIL" at 12987.46,6048 h60
  text "MIN. VIA PAD SIZE:" at 11736.46,5916 h60
  text "24" at 12802.71,5916 h60
  text "MIL" at 12987.46,5916 h60
  text "0.05mm (2MIL)" at 12431.46,5774.29 h60
  text "MINIMUM ANNULAR RING" at 11407.23,5770 h60
  text "EXTERNAL" at 13139.46,5770 h60
  text "PER" at 11607.23,5652 h60
  text "IPC-D-275 CLASS 2 LEVEL C" at 11827.23,5652 h60
  text "MIL, HOLES" at 13315.46,5539.71 h60
  text "+/-" at 12923,5539 h60
  text "+/-" at 13777,5539 h60
  text "REGISTRATION TOLERANCES:" at 11407.23,5534 h60
  text "METAL" at 12607,5534 h60
  text "5" at 13183.2,5534 h60
  text "3" at 14016.2,5534 h60
  text "MIL" at 14132.46,5534 h60
  text "MATERIAL:" at 11332.46,5324.54 h60
  text "FR-4 High Tg" at 12318.9,5184.21 h60
  text "FR-408" at 11753.46,5175.64 h60
  text "X" at 12165.46,5175.64 h60
  text "OTHER" at 13241.46,5175.64 h60
  text "62 MIL (1.6mm) +/-10%" at 12073.56,5012.92 h60
  text "THICKNESS:" at 11407.23,5008.64 h60
  text "X" at 11945.4,5008.64 h60
  text "OTHER" at 13358.46,5008.64 h60
  text "TOLERANCE:" at 11407.23,4850.64 h60
  text "X" at 12246.53,4850.64 h60
  text "ANSI IPC-6012 TYPE 3 CLASS 2" at 12433.48,4850.64 h60
  text "OTHER +/-" at 12433.46,4694.64 h60
  text "BOW & TWIST:" at 11407.23,4537.64 h60
  text "X" at 12246.53,4537.64 h60
  text "ANSI IPC-6012 TYPE 3 CLASS 2" at 12433.48,4537.64 h60
  text "OTHER +/-" at 12433.46,4379.13 h60
  text "COPPER THICKNESS (FINISHED):" at 11332.46,4243.64 h60
  text "1.4MIL (1oz)" at 12212.46,4090.92 h60
  text "2MIL (1.4oz)" at 12979.46,4090.92 h60
  text "2.8MIL (2oz)" at 13706.46,4090.92 h60
  text "OUTER:" at 11689.46,4086.64 h60
  text "X" at 12084,4086 h60
  text "1.4MIL (1oz)" at 12212.46,3933.92 h60
  text "2.8MIL (2oz)" at 12979.46,3933.92 h60
  text "N/A" at 13706,3934.29 h60
  text "INNER SIGNAL:" at 11400.38,3929.64 h60
  text "X" at 12085.42,3929.64 h60
  text "DRILLING:" at 11332.46,3790.64 h60
  text "REFERENCE:" at 11407.23,3673.64 h60
  text "X" at 12055.46,3673.64 h60
  text "AS SHOWN" at 12242.46,3673.64 h60
  text "X" at 12956.46,3673.64 h60
  text "NC_DRILL FILES" at 13093.46,3673.64 h60
  text "PTH MIN COPPER THICKNESS:" at 11407.23,3515.64 h60
  text "X" at 12757.46,3515.64 h60
  text "1MIL" at 12894.46,3515.64 h60
  text "OTHER" at 13391.46,3515.64 h60
  text "BOARD FINISH:" at 11332.46,3356.64 h60
  text "SILKSCREEN:" at 11487.68,3238.64 h60
  text "X" at 12436.46,3238.64 h60
  text "TOP" at 12562.46,3238.64 h60
  text "X" at 12946.46,3238.64 h60
  text "BOTTOM" at 13073.46,3238.64 h60
  text "SILKSCREEN COLOR:" at 11487.68,3071.64 h60
  text "X" at 12435.42,3071.64 h60
  text "WHITE" at 12562.46,3071.64 h60
  text "OTHER" at 13073.46,3071.64 h60
  text "SOLDER RESIST COLOR:" at 11487.68,2901.64 h60
  text "X" at 12650,2745 h60
  text "GREEN" at 12182.46,2742.44 h60
  text "BLUE" at 12773.46,2742.44 h60
  text "OTHER" at 13311.46,2742.44 h60
  text "IMMERSION GOLD (ENIG)" at 12393.46,2553.92 h60
  text "ENEPIG" at 13731,2550.64 h60
  text "SURFACE FINISH:" at 11332.46,2549.64 h60
  text "IMM. TIN/SILVER OR EQUIV" at 11662,2392.64 h60
  text "OTHER" at 13093.46,2392.64 h60
  text "X" at 11505,2390 h60
  text "ARRAY/PANEL:" at 11332.46,2213.64 h60
  text "CUT AND TRIM PER MECH LAYER 1" at 12393.46,2209.35 h60
  text "N.C. ROUTE" at 12393.46,2057.64 h60
  text "X" at 13072.46,2057.64 h60
  text "V. SCORE" at 13259.46,2057.64 h60
  text "CERTIFICATION:" at 11332.46,1920.64 h60
  text "MATERIALS AND WORKMANSHIP FOR ALL PCBS" at 12057.46,1920.64 h60
  text "TO MEET OR EXCEED THE REQUIREMENTS OF:" at 12057.46,1822.64 h60
  text "X" at 11683.96,1686.13 h60
  text "ANSI IPC-A-600F CLASS ->" at 11822.96,1686.13 h60
  text "X" at 13462.02,1686.13 h60
  text "2" at 13580.96,1686.14 h60
  text "1" at 13265.96,1684.64 h60
  text "3" at 13934.96,1684.64 h60
  text "X" at 11686.02,1526.64 h60
  text "UL 94V-0" at 11822.96,1526.64 h60
  text "X" at 12498.02,1526.64 h60
  text "RoHS" at 12634.96,1526.64 h60
  text "OTHER" at 13279.36,1526.64 h60
  text "PER ORDER" at 13676.42,1526.64 h60
  text "ADDITIONAL REQUIREMENTS:" at 11332.46,1385.64 h60
  text "MICROSECTION:" at 11407.23,1270.64 h60
  text "YES" at 12312.96,1270.64 h60
  text "REQUIRED" at 13174.46,1114.49 h60
  text "BARE BOARD ELEC. TEST:" at 11407.23,1111.64 h60
  text "NONE" at 12712.96,1111.64 h60
  text "X" at 13047.46,1111.64 h60
  text "PER ORDER" at 13766.46,1111.64 h60
  text "MANUFACTURER'S UL:" at 11407.23,954.64 h60
  text "RAIL" at 12572.96,950.35 h60
  text "METAL" at 13064.77,950.35 h60
  text "X" at 13440,950 h60
  text "SILK" at 13576.46,950.35 h60
  text ".Layer_Name" at 577,-858.49 h60
M11 Gerber Information:
  lines w10: -292,-930.17 6308,-930.17 ; -292,-726.83 6310,-726.83 ; -292,-523.5 -292,-1133.5 3713,-1133.5 6310,-1133.5 6310,-523.5 -291.5,-523.5 -291.5,-1133.5 1284,-1133.5 ; 2173,-1133.5 2173,-523.5 ; 3440,-726.83 3440,-523.5 ; 4280,-726.83 4280,-523.5 ; 4902,-1140 4902,-937.17
  text "ALL ARTWORK VIEWED FROM TOP SIDE" at -228.5,-655.67 h60
  text "BOARD #:" at 2248,-655.67 h60
  text ".PRJ_Number" at 2793.5,-655.67 h60
  text "REV:" at 3638,-655.67 h60
  text ".PCB_Rev" at 3929.5,-655.67 h60
  text "SVN REV:" at 4476,-655.67 h60
  text ".VersionControl_RevNumber" at 4982,-655.67 h60
  text "LAYER NAME =" at -228.5,-858.49 h60
  text "PLOT NAME =" at -228.5,-1064.34 h60
  text ".plot_File_Name" at 577,-1064.34 h60
  text "GENERATED    :" at 2250,-1064.34 h60
  text ".Print_Date" at 3119.5,-1064.34 h60
  text ".Print_Time" at 3848.5,-1064.34 h60
  text "TEXAS INSTRUMENTS" at 5113,-1064.34 h60
M12 Stackup:
  lines w6: 11365,7693 14220,7693 ; 11365,7805.6 14220,7805.6 ; 11305,6976 ccw(c11341,6976) 11341,6940 14244,6940 ccw(c14244,6976) 14280,6976 14280,7904 ccw(c14244,7904) 14244,7940 11341,7940 ccw(c11341,7904) 11305,7904 11305,6976
  text "Layer Stack Up Detail for: PMP10282 REVA.PcbDoc" at 11365,7835 h51
  text "Layer" at 11365,7763.6 h26
  text "Gerber" at 12364.47,7763.6 h26
  text "Copper" at 13018.18,7763.6 h26
  text "Dielectric" at 13714.35,7763.6 h26
  text "Name" at 11365,7711.6 h26
  text "Document" at 12364.47,7711.6 h26
  text "Thickness" at 13018.18,7711.6 h26
  text "Material" at 13714.35,7711.6 h26
  text "Top Solder Mask" at 11365,7637.92 h36
  text "(.GTS)" at 12364.47,7637.92 h36
  text "Solder Resist" at 13714.35,7637.92 h36
  text "Top Layer" at 11365,7533.75 h36
  text "(.GTL)" at 12364.47,7533.75 h36
  text "1.4mil" at 13018.18,7533.75 h36
  text "FR-4" at 13714.35,7481.67 h36
  text "MidLayer1" at 11365,7429.58 h36
  text "(.G1)" at 12364.47,7429.58 h36
  text "1.4mil" at 13018.18,7429.58 h36
  text "FR-4" at 13714.35,7377.5 h36
  text "MidLayer2" at 11365,7325.42 h36
  text "(.G2)" at 12364.47,7325.42 h36
  text "1.4mil" at 13018.18,7325.42 h36
  text "FR-4" at 13714.35,7273.33 h36
  text "Bottom Layer" at 11365,7221.25 h36
  text "(.GBL)" at 12364.47,7221.25 h36
  text "1.4mil" at 13018.18,7221.25 h36
  text "Bottom Solder Mask" at 11365,7117.08 h36
  text "(.GBS)" at 12364.47,7117.08 h36
  text "Solder Resist" at 13714.35,7117.08 h36
  text ".Layer_Name" at 577,-858.49 h60
M13 Component Bodies Top:
  text ".Layer_Name" at 577,-858.49 h60
M14 Component Bodies Bottom:
  text ".Layer_Name" at 577,-858.49 h60
M15 Courtyards Top:
  text ".Layer_Name" at 577,-858.49 h60
M16 Courtyards Bottom:
  text ".Layer_Name" at 577,-858.49 h60
Drill Drawing:
  text ".legend" at 5122.5,725.5 h60
  text "Drill Table" at 5147.5,540.5 h60
  text ".Layer_Name" at 577,-858.49 h60

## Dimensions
0,0 to 0,1181.1 on M2 Board Dimensions
0,0 to 3149.61,0 on M2 Board Dimensions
